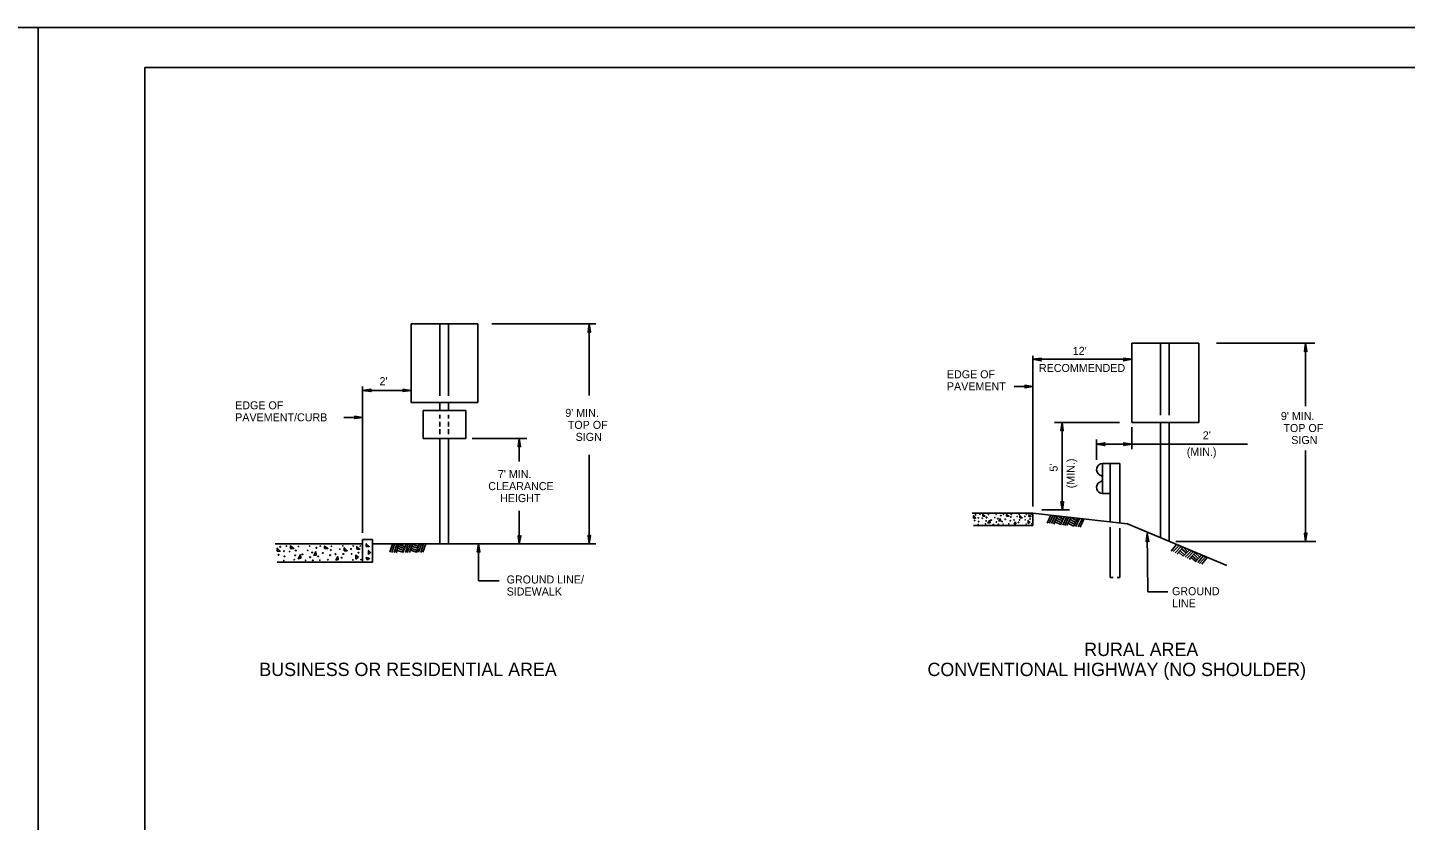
# Model space of a CAD drawing. Extents: x 644358 to 648627, y 294594 to 295782.
# Drawn here: x 646877 to 647394, y 294891 to 295188 of the extents above; entities that cross this region are included whole.
import ezdxf

# ---------------------------------------------------------------- set-up
doc = ezdxf.new("R2010")
doc.units = 0
for name, color, linetype in [('1', 7, 'Continuous'), ('2', 7, 'Continuous'), ('4', 7, 'Continuous'), ('PLT-BNDY', 7, 'Continuous')]:
    doc.layers.add(name, color=color, linetype=linetype)

msp = doc.modelspace()

# ---------------------------------------------------------------- linework, layer by layer
at = {"layer": '1'}
for p, q in [((646921.31, 295172.63), (647707.31, 295172.63)), ((646921.31, 295172.63), (646921.31, 294608.63)), ((647260.94, 295005), (647259.56, 295002)), ((647261.81, 295004.88), (647260.31, 295002)), ((647262.56, 295004.75), (647261.19, 295001.88)), ((647263.44, 295004.75), (647261.94, 295001.75)), ((647264.94, 295002.13), (647262.69, 295003.25)), ((647265.31, 295002.88), (647263.06, 295003.88)), ((647265.56, 295003.5), (647263.44, 295004.63)), ((647265.94, 295004.38), (647264.56, 295001.38)), ((647265.19, 295004.38), (647264.81, 295004.5)), ((647266.81, 295004.25), (647265.44, 295001.25)), ((647267.56, 295004.13), (647266.19, 295001.13)), ((647268.44, 295004.13), (647266.94, 295001.13)), ((647269.94, 295001.63), (647267.69, 295002.63)), ((647270.19, 295002.25), (647268.06, 295003.5)), ((647270.56, 295003), (647268.44, 295004.13)), ((647269.31, 295003.88), (647268.94, 295004.13)), ((647270.94, 295003.75), (647269.56, 295000.88)), ((647271.69, 295003.75), (647270.31, 295000.75)), ((647272.69, 295003.63), (647271.19, 295000.63)), ((647273.31, 295003.5), (647271.94, 295000.5)), ((647262.44, 295001.75), (647262.06, 295001.88)), ((647264.56, 295001.5), (647262.44, 295002.5)), ((647269.56, 295000.88), (647267.31, 295002)), ((647297.31, 294976.25), (647297.06, 294998.13)), ((647014.19, 294994.13), (647013.19, 294991.13)), ((647014.94, 294994.13), (647013.94, 294991)), ((647015.81, 294994.13), (647014.81, 294991)), ((647016.56, 294994.13), (647015.56, 294991)), ((647018.31, 294991.75), (647016.19, 294992.63)), ((647018.69, 294992.5), (647016.44, 294993.25)), ((647018.94, 294993.13), (647016.56, 294994)), ((647018.31, 294994), (647017.94, 294994.13)), ((647019.31, 294994.13), (647018.06, 294991)), ((647020.06, 294994.13), (647019.06, 294991)), ((647020.94, 294994.13), (647019.69, 294991)), ((647021.69, 294994.13), (647020.56, 294991)), ((647023.44, 294991.75), (647021.06, 294992.63)), ((647023.69, 294992.63), (647021.31, 294993.38)), ((647023.94, 294993.25), (647021.69, 294994.13)), ((647022.44, 294994), (647022.19, 294994.25)), ((647024.19, 294994.13), (647023.19, 294991)), ((647025.06, 294994.25), (647023.94, 294991.13)), ((647025.81, 294994.25), (647024.81, 294991)), ((647026.69, 294994.25), (647025.56, 294991.13)), ((647046.44, 294980.38), (647046.44, 294994.25)), ((647308.06, 294994), (647305.94, 294991.5)), ((647308.94, 294993.63), (647306.69, 294991.38)), ((647309.69, 294993.25), (647307.44, 294990.88)), ((647310.44, 294993), (647308.19, 294990.5)), ((647311.69, 294990.75), (647309.81, 294992.5)), ((647312.06, 294991.38), (647310.44, 294993)), ((647015.94, 294991), (647015.56, 294991.13)), ((647018.19, 294991.13), (647015.81, 294991.75)), ((647023.19, 294991.13), (647020.94, 294991.88)), ((647308.56, 294990.38), (647308.31, 294990.63)), ((647310.56, 294989.63), (647308.81, 294991.25)), ((647311.06, 294990.13), (647309.31, 294991.75)), ((647312.69, 294991.88), (647310.56, 294989.63)), ((647313.44, 294991.5), (647311.31, 294989.25)), ((647314.19, 294991.25), (647311.94, 294988.88)), ((647314.94, 294991), (647312.81, 294988.5)), ((647313.19, 294988.5), (647312.81, 294988.63)), ((647315.19, 294987.63), (647313.44, 294989.13)), ((647315.69, 294988.13), (647313.81, 294989.75)), ((647316.19, 294988.63), (647314.44, 294990.38)), ((647316.69, 294989.25), (647314.94, 294990.88)), ((647317.31, 294990), (647315.06, 294987.5)), ((647315.69, 294990.5), (647315.44, 294990.75)), ((647318.06, 294989.75), (647315.94, 294987.25)), ((647318.81, 294989.38), (647316.56, 294986.88)), ((647319.44, 294989.13), (647317.44, 294986.63))]:
    msp.add_line(p, q, dxfattribs=at)
for points in [[(647264.81, 295036.88), (647265.06, 295036.88), (647265.19, 295039.75), (647264.81, 295036.88), (647264.69, 295036.63), (647265.19, 295039.75), (647265.31, 295036.88), (647265.44, 295036.88), (647265.19, 295039.75), (647265.56, 295036.63), (647265.44, 295036.88)], [(647265.56, 295009.88), (647265.44, 295009.75), (647265.31, 295006.88), (647265.56, 295009.88), (647265.69, 295010), (647265.31, 295006.88), (647265.06, 295009.75), (647264.94, 295009.88), (647265.31, 295006.88), (647264.69, 295010), (647264.94, 295009.88)], [(647296.81, 294995.25), (647296.94, 294995.38), (647297.06, 294998.13), (647296.81, 294995.25), (647296.69, 294995), (647297.06, 294998.13), (647297.31, 294995.38), (647297.56, 294995.25), (647297.06, 294998.13), (647297.69, 294995), (647297.56, 294995.25)], [(647046.06, 294991.25), (647046.31, 294991.38), (647046.44, 294994.25), (647046.06, 294991.25), (647045.94, 294991.13), (647046.44, 294994.25), (647046.56, 294991.38), (647046.69, 294991.25), (647046.44, 294994.25), (647046.94, 294991.13), (647046.69, 294991.25)]]:
    msp.add_lwpolyline(points, dxfattribs=at)
for points in [[(647231.94, 295003.88), (647231.94, 295004.75), (647232.69, 295003.88)], [(647235.44, 295004.63), (647235.44, 295005.25), (647236.19, 295004.63)], [(647238.06, 295003.13), (647238.19, 295002.13), (647237.31, 295002)], [(647241.94, 295003.75), (647242.06, 295002.88), (647241.44, 295002.75)], [(647244.31, 295004.63), (647244.31, 295005.25), (647245.19, 295004.63)], [(647249.31, 295004), (647249.31, 295004.88), (647250.19, 295004)], [(647252.44, 295001.88), (647252.44, 295003), (647253.06, 295002.38)], [(647252.69, 295004.5), (647252.69, 295005.13), (647253.44, 295004.5)], [(647247.69, 295002.5), (647247.81, 295001.75), (647247.19, 295001.63)], [(646970.94, 294991.5), (646970.94, 294992.63), (646972.06, 294991.5)], [(646975.94, 294992.5), (646975.94, 294993.5), (646977.19, 294992.5)], [(646988.69, 294992.5), (646988.69, 294993.38), (646989.94, 294992.5)], [(646996.06, 294991.63), (646996.06, 294992.75), (646997.19, 294991.63)], [(647000.81, 294992.25), (647000.81, 294993.25), (647001.94, 294992.25)], [(647004.31, 294993.25), (647004.31, 294994.25), (647005.44, 294993.25)], [(646979.69, 294990.25), (646979.81, 294988.88), (646978.81, 294988.63)], [(646985.44, 294991.38), (646985.56, 294990), (646984.69, 294989.88)], [(646993.69, 294989.5), (646993.81, 294988.38), (646992.94, 294988.13)], [(647000.44, 294988.5), (647000.44, 294990), (647001.31, 294989.25)], [(647004.69, 294988.25), (647004.31, 294989.13), (647005.56, 294988.75)], [(647005.19, 294990.25), (647005.19, 294991.75), (647005.94, 294991)]]:
    msp.add_lwpolyline(points, close=True, dxfattribs=at)
for centre, radius in [((647232.32, 295002.98), 0.0979), ((647232.71, 295005.07), 0.0979), ((647233.72, 295003.94), 0.0979), ((647233.85, 295002.58), 0.0979), ((647234.37, 295005.25), 0.056), ((647235.2, 295003.82), 0.056), ((647236.65, 295002.84), 0.0979), ((647236.79, 295004.1), 0.0979), ((647237.47, 295005.15), 0.056), ((647238.54, 295003.13), 0.0979), ((647239.9, 295004.13), 0.056), ((647240.41, 295005.28), 0.056), ((647241.04, 295003.61), 0.0979), ((647242.16, 295004.82), 0.0979), ((647242.62, 295002.58), 0.0979), ((647243.14, 295005.25), 0.056), ((647243.82, 295003.46), 0.0979), ((647245.72, 295002.89), 0.0979), ((647245.91, 295004.25), 0.0979), ((647246.07, 295005.2), 0.056), ((647247.14, 295003.18), 0.0979), ((647248.28, 295004.46), 0.056), ((647249.01, 295005.33), 0.056), ((647249.19, 295003.21), 0.0979), ((647251.18, 295004.52), 0.0979), ((647251.3, 295003.23), 0.056), ((647251.74, 295005.3), 0.056), ((647253.11, 295003.54), 0.0979), ((647253.58, 295005.26), 0.056), ((647233.68, 295001.52), 0.056), ((647236.39, 295001.72), 0.056), ((647239.37, 295001.57), 0.056), ((647240.52, 295002.39), 0.0979), ((647241.24, 295001.56), 0.0979), ((647243.05, 295001.6), 0.056), ((647245.17, 295001.72), 0.056), ((647248.74, 295002.24), 0.0979), ((647251.65, 295001.65), 0.056), ((647253.77, 295001.77), 0.056), ((646972.04, 294993.11), 0.141), ((646974.42, 294993.37), 0.0806), ((646978.88, 294993.24), 0.0806), ((646983.12, 294993.42), 0.0806), ((646985.64, 294992.76), 0.141), ((646987.06, 294993.37), 0.0806), ((646991.27, 294993.31), 0.0806), ((646994.45, 294992.24), 0.0806), ((646995.51, 294993.49), 0.0806), ((646998.63, 294992.32), 0.141), ((646999.44, 294993.44), 0.0806), ((647002.09, 294993.4), 0.0806), ((646971.47, 294990.12), 0.141), ((646973.49, 294991.49), 0.141), ((646973.43, 294988.01), 0.0806), ((646973.67, 294989.53), 0.141), ((646975.62, 294991.33), 0.0806), ((646977.34, 294988.29), 0.0806), ((646977.7, 294989.91), 0.141), ((646977.91, 294991.73), 0.141), ((646980.43, 294990.32), 0.141), ((646981.62, 294988.07), 0.0806), ((646982.39, 294991.77), 0.0806), ((646983.27, 294989.26), 0.141), ((646984.03, 294991.01), 0.141), ((646984.32, 294988.07), 0.141), ((646986.3, 294989.53), 0.141), ((646986.93, 294988.12), 0.0806), ((646988.03, 294990.81), 0.141), ((646989.97, 294988.29), 0.0806), ((646990.77, 294989.99), 0.141), ((646991.04, 294991.94), 0.141), ((646992.81, 294990.4), 0.141), ((646995.12, 294989.04), 0.141), ((646995.77, 294990.44), 0.141), ((646998.81, 294990.48), 0.0806), ((646999.31, 294988.19), 0.0806), ((647001.41, 294990.92), 0.141), ((647002.35, 294988.36), 0.0806)]:
    msp.add_circle(centre, radius, dxfattribs=at)
at = {"layer": '2'}
for p, q in [((647021.19, 295076.63), (647021.19, 295047.13)), ((647046.19, 295076.63), (647021.19, 295076.63)), ((647031.94, 295076.63), (647031.94, 295049.63)), ((647035.19, 295076.63), (647035.19, 295049.63)), ((647046.19, 295047.13), (647046.19, 295076.63)), ((647291.31, 295069.38), (647291.31, 295039.75)), ((647316.31, 295069.38), (647291.31, 295069.38)), ((647302.06, 295069.38), (647302.06, 295042.38)), ((647305.31, 295069.38), (647305.31, 295042.38)), ((647316.31, 295039.75), (647316.31, 295069.38)), ((647021.19, 295047.13), (647046.19, 295047.13)), ((647025.69, 295044.13), (647041.69, 295044.13)), ((647025.69, 295033.75), (647025.69, 295044.13)), ((647031.94, 295047.13), (647031.94, 295044.13)), ((647035.19, 295047.13), (647035.19, 295044.13)), ((647041.69, 295033.75), (647041.69, 295044.13)), ((647031.94, 295042.5), (647031.94, 295041.13)), ((647031.94, 295039.88), (647031.94, 295038.13)), ((647035.19, 295042.5), (647035.19, 295041.13)), ((647035.19, 295040), (647035.19, 295038.25)), ((647291.31, 295039.75), (647316.31, 295039.75)), ((647302.06, 295039.75), (647302.06, 294996.38)), ((647305.31, 295039.75), (647305.31, 294995.13)), ((647025.69, 295033.75), (647041.69, 295033.75)), ((647031.94, 295037.13), (647031.94, 295035.38)), ((647031.94, 295033.75), (647031.94, 294994.25)), ((647035.19, 295037.25), (647035.19, 295035.38)), ((647035.19, 295033.75), (647035.19, 294994.25)), ((647280.31, 295024.38), (647286.81, 295024.38)), ((647280.31, 295024.38), (647280.31, 295013.13)), ((647283.19, 295024.38), (647283.19, 295002.38)), ((647286.81, 295024.38), (647286.81, 295002)), ((647280.31, 295013.13), (647283.19, 295013.13)), ((647254.19, 295005.75), (647231.44, 295005.75)), ((647254.19, 295005.75), (647254.19, 295001.13)), ((647254.19, 295005.75), (647289.69, 295001.75)), ((647254.19, 295001.13), (647231.94, 295001.13)), ((647283.19, 295000.5), (647283.19, 294981.63)), ((647286.81, 295000.13), (647286.81, 294981.63)), ((647289.69, 295001.75), (647326.81, 294986.13)), ((647002.94, 294994.25), (646970.19, 294994.25)), ((647002.94, 294995.88), (647002.94, 294987.38)), ((647002.94, 294995.88), (647006.69, 294995.88)), ((647006.69, 294995.88), (647006.69, 294987.38)), ((647006.69, 294994.25), (647090.39, 294994.25)), ((647006.69, 294987.38), (646970.94, 294987.38)), ((647283.19, 294981.63), (647284.31, 294981.63)), ((647285.81, 294981.63), (647286.81, 294981.63))]:
    msp.add_line(p, q, dxfattribs=at)
for centre, radius, start, end in [((647280.3, 295022.02), 2.25, 89.9698, 242.4823), ((647278.94, 295018.7), 1.36, 283.7991, 76.2589), ((647280.3, 295015.38), 2.25, 117.4792, 270.0302)]:
    msp.add_arc(centre, radius, start, end, dxfattribs=at)
at = {"layer": '4'}
for p, q in [((647090.39, 295076.63), (647051.4, 295076.63)), ((647087.83, 295076.63), (647087.83, 295049.78)), ((647254.19, 295064.63), (647254.19, 295008.28)), ((647359.86, 295069.38), (647323.03, 295069.38)), ((647356.41, 295069.38), (647356.41, 295045.82)), ((647291.31, 295063.38), (647254.19, 295063.38)), ((647002.94, 295053.13), (647002.94, 294998.38)), ((647021.19, 295051.63), (647002.94, 295051.63)), ((647247.19, 295053.13), (647254.19, 295053.13)), ((646995.94, 295041.5), (647002.94, 295041.5)), ((647286.69, 295039.75), (647262.31, 295039.75)), ((647265.19, 295039.75), (647265.19, 295007)), ((647064.56, 295033.75), (647044.06, 295033.75)), ((647061.69, 295033.75), (647061.69, 295025.1)), ((647291.31, 295037.88), (647291.31, 295029.75)), ((647278.06, 295033.38), (647278.06, 295025.75)), ((647334.64, 295031.63), (647278.06, 295031.63)), ((647356.41, 294995.13), (647356.41, 295029.17)), ((647087.83, 294994.25), (647087.83, 295027.54)), ((647061.69, 295006.63), (647061.69, 294994.25)), ((647267.94, 295007), (647257.5, 295007)), ((647360.25, 294995.13), (647307.75, 294995.13)), ((647046.44, 294980.38), (647054.19, 294980.38)), ((647297.31, 294976.25), (647304.69, 294976.25))]:
    msp.add_line(p, q, dxfattribs=at)
for points in [[(647087.58, 295073.63), (647087.71, 295073.75), (647087.83, 295076.63), (647087.58, 295073.63), (647087.46, 295073.5), (647087.83, 295076.63), (647087.96, 295073.75), (647088.21, 295073.63), (647087.83, 295076.63), (647088.33, 295073.5), (647088.21, 295073.63)], [(647356.16, 295066.38), (647356.28, 295066.5), (647356.41, 295069.38), (647356.16, 295066.38), (647356.03, 295066.25), (647356.41, 295069.38), (647356.53, 295066.5), (647356.78, 295066.38), (647356.41, 295069.38), (647356.91, 295066.25), (647356.78, 295066.38)], [(647257.19, 295062.88), (647257.06, 295063.13), (647254.19, 295063.38), (647257.19, 295062.88), (647257.31, 295062.75), (647254.19, 295063.38), (647257.06, 295063.5), (647257.19, 295063.63), (647254.19, 295063.38), (647257.31, 295063.75), (647257.19, 295063.63)], [(647288.31, 295063.63), (647288.44, 295063.5), (647291.31, 295063.38), (647288.31, 295063.63), (647288.19, 295063.75), (647291.31, 295063.38), (647288.44, 295063.13), (647288.31, 295063), (647291.31, 295063.38), (647288.19, 295062.75), (647288.31, 295063)], [(647005.94, 295051.38), (647005.94, 295051.63), (647002.94, 295051.63), (647005.94, 295051.38), (647006.06, 295051.25), (647002.94, 295051.63), (647005.94, 295051.75), (647005.94, 295052), (647002.94, 295051.63), (647006.06, 295052.13), (647005.94, 295052)], [(647018.19, 295052), (647018.31, 295051.75), (647021.19, 295051.63), (647018.19, 295052), (647018.06, 295052.13), (647021.19, 295051.63), (647018.31, 295051.63), (647018.19, 295051.38), (647021.19, 295051.63), (647018.06, 295051.25), (647018.19, 295051.38)], [(647251.31, 295053.5), (647251.44, 295053.25), (647254.19, 295053.13), (647251.31, 295053.5), (647251.19, 295053.63), (647254.19, 295053.13), (647251.44, 295053), (647251.31, 295052.75), (647254.19, 295053.13), (647251.19, 295052.63), (647251.31, 295052.75)], [(647000.06, 295041.88), (647000.19, 295041.63), (647002.94, 295041.5), (647000.06, 295041.88), (646999.94, 295042), (647002.94, 295041.5), (647000.19, 295041.38), (647000.06, 295041.13), (647002.94, 295041.5), (646999.94, 295041.13), (647000.06, 295041.13)], [(647061.44, 295030.75), (647061.56, 295030.88), (647061.69, 295033.75), (647061.44, 295030.75), (647061.31, 295030.63), (647061.69, 295033.75), (647061.81, 295030.88), (647062.06, 295030.75), (647061.69, 295033.75), (647062.19, 295030.63), (647062.06, 295030.75)], [(647280.94, 295031.25), (647280.81, 295031.5), (647278.06, 295031.63), (647280.94, 295031.25), (647281.19, 295031.13), (647278.06, 295031.63), (647280.81, 295031.75), (647280.94, 295032), (647278.06, 295031.63), (647281.19, 295032.13), (647280.94, 295032)], [(647288.31, 295032), (647288.44, 295031.75), (647291.31, 295031.63), (647288.31, 295032), (647288.19, 295032.13), (647291.31, 295031.63), (647288.44, 295031.5), (647288.31, 295031.25), (647291.31, 295031.63), (647288.19, 295031.13), (647288.31, 295031.25)], [(647356.16, 294998.13), (647356.28, 294998), (647356.41, 294995.13), (647356.16, 294998.13), (647356.03, 294998.25), (647356.41, 294995.13), (647356.53, 294998), (647356.78, 294998.13), (647356.41, 294995.13), (647356.91, 294998.25), (647356.78, 294998.13)], [(647062.06, 294997.13), (647061.94, 294997), (647061.69, 294994.25), (647062.06, 294997.13), (647062.31, 294997.25), (647061.69, 294994.25), (647061.56, 294997), (647061.44, 294997.13), (647061.69, 294994.25), (647061.31, 294997.25), (647061.44, 294997.13)], [(647087.58, 294997.25), (647087.71, 294997.13), (647087.83, 294994.25), (647087.58, 294997.25), (647087.46, 294997.38), (647087.83, 294994.25), (647087.96, 294997.13), (647088.21, 294997.25), (647087.83, 294994.25), (647088.33, 294997.38), (647088.21, 294997.25)]]:
    msp.add_lwpolyline(points, dxfattribs=at)
at = {"layer": 'PLT-BNDY'}
for points in [[(646040.31, 295187.63), (646881.31, 295187.63), (646881.31, 294593.63), (646040.31, 294593.63)], [(646881.31, 295187.63), (647722.31, 295187.63), (647722.31, 294593.63), (646881.31, 294593.63)]]:
    msp.add_lwpolyline(points, close=True, dxfattribs=at)

# ---------------------------------------------------------------- texts
at = {"layer": '1'}
for s, p in [("12'", (647269.13, 295065.03)), ('RECOMMENDED', (647256.44, 295058.61)), ("2'", (647009.3, 295053.67)), ('EDGE OF', (647221.94, 295056.25)), ('PAVEMENT', (647221.94, 295051.75)), ('EDGE OF', (646955.19, 295044.63)), ("9' MIN.", (647078.92, 295041.8)), ('PAVEMENT/CURB', (646955.19, 295040.13)), ('TOP OF', (647079.87, 295037.3)), ("9' MIN.", (647347.13, 295040.62)), ('TOP OF', (647348.08, 295036.12)), ('SIGN', (647082.8, 295032.8)), ("2'", (647317.85, 295033.39)), ('SIGN', (647351.01, 295031.62)), ("7' MIN.", (647053.67, 295018.86)), ('CLEARANCE', (647050.05, 295014.36)), ('HEIGHT', (647054.48, 295009.86)), ('GROUND LINE/', (647056.94, 294979.38)), ('SIDEWALK', (647056.94, 294974.88)), ('GROUND', (647306.31, 294975)), ('LINE', (647306.31, 294970.5))]:
    msp.add_text(s, height=3, dxfattribs=at).set_placement(p)
for s, p in [("5'", (647263.44, 295021.28)), ('(MIN.)', (647269.87, 295015.06))]:
    msp.add_text(s, height=3, rotation=90, dxfattribs=at).set_placement(p)
at = {"layer": '2'}
for s, height, p in [('(MIN.)', 3, (647311.85, 295027.2)), ('RURAL AREA', 5, (647273.43, 294952.2)), ('BUSINESS OR RESIDENTIAL AREA', 5, (646964.26, 294944.72)), ('CONVENTIONAL HIGHWAY (NO SHOULDER)', 5, (647214.67, 294944.7))]:
    msp.add_text(s, height=height, dxfattribs=at).set_placement(p)

doc.saveas('drawing.dxf')
